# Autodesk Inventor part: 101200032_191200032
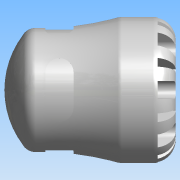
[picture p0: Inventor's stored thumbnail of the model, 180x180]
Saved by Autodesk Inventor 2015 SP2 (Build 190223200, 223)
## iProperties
Created: 2016-12
Part Number: 101200032_191200032
Material: PVC-Piping
Description: PLASSON END PLUG 32 SERIES 1
Document SubType Name: Modeling
Designer: KIM
Mass: 57.8335 g
Surface Area: 121.129 cm^2
Volume: 41.3096 cm^3
Density: 1.4 g/cm^3
Appearance: Smooth - White
Author: KIM
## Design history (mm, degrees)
derived "1012.ipt"
feature "Solid1::1012.ipt"
tag "TaggingFeature1"
body "Solid1"
other parameters: "d0" = 68, "d1" = 22.26, "d2" = 32, "d4" = 58, "d6" = 53, "d7" = 58.3, "d8" = 49.3, "d13" = 7.2, "d14" = 7.2, "d15" = 0, "d17" = 360 deg, "d19" = 8 deg, "d20" = 0.64, "d21" = 0.64, "d22" = 8 deg, "d24" = 0, "d26" = 360 deg, "d32" = 5.8, "d33" = 5.8, "d34" = 7.04, "d35" = 11.2, "d36" = 14.112, "d37" = 0, "d42" = 360 deg, "d45" = 9.52, "d46" = 0.64, "d48" = 0, "d49" = 0.58, "d_" = 32, "E_" = 58, "H_" = 68, "l_" = 53, "d9" = 9, "d11" = 58
